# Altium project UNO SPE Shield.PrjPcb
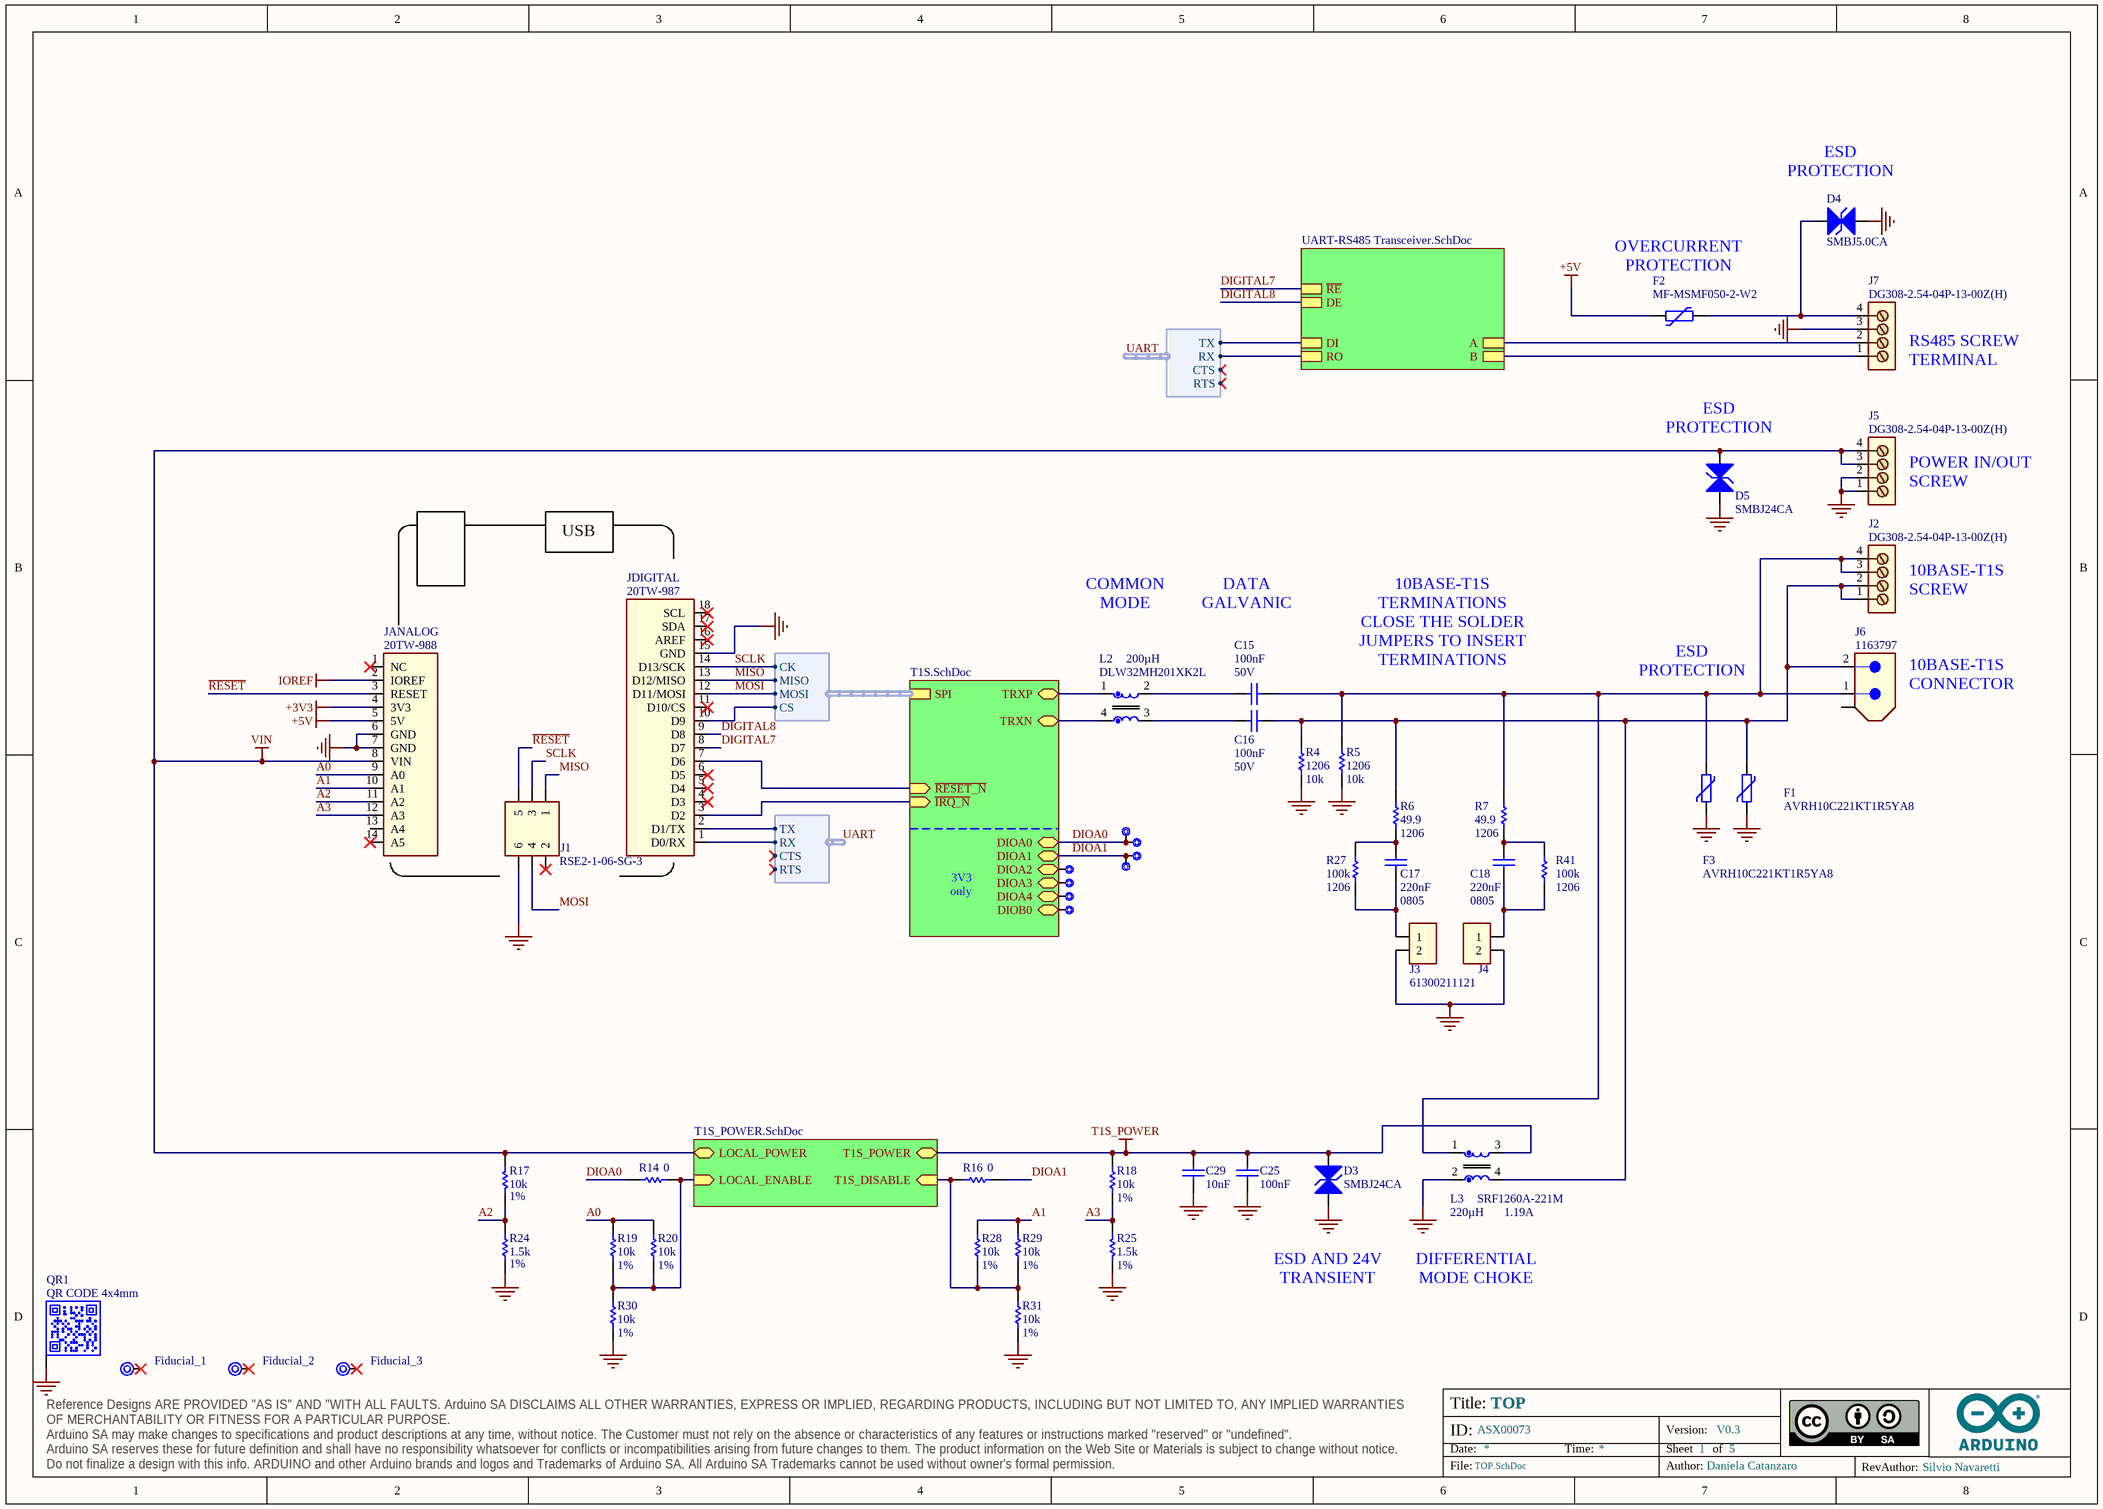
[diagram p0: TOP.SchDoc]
ASSEMBLY_BGA: _; ASSEMBLY_PRESSFIT: _; ASSEMBLY_SMD: X; ASSEMBLY_THT: X; BOARD_CODENAME: T2TOS; BOARD_INFO_AUTHOR: Daniela Catanzaro; BOARD_INFO_AUTHOR_REV: Silvio Navaretti; BOARD_INFO_Er: _; BOARD_INFO_FLEX: _; BOARD_INFO_FR4: X; BOARD_INFO_FR4_HTG: _; BOARD_INFO_IPC1: _; BOARD_INFO_IPC2: X; BOARD_INFO_IPC3: _; BOARD_INFO_IPC_NA: X; BOARD_INFO_NUMBER_OF_LAYERS: 4; BOARD_INFO_PCB_SIZE: 68.58x53.34mm; BOARD_INFO_POLYMIDE: _; BOARD_INFO_RIGID: X; BOARD_INFO_RIGID/FLEX: _; BOARD_INFO_TBD: _; BOARD_INFO_THICKNESS: 1.6mm; DRILLS_BLIND: _; DRILLS_BURIED: _; DRILLS_COPPER_FILLING: _; DRILLS_FULL: X; DRILLS_LASER: _; DRILLS_PRESSFIT: _; DRILLS_RESIN_FILLING: _; DRILLS_SLOT: _; DRILLS_SOLDER_FILLING: X; FINISH_ADJUSTMENTS: _; FINISH_EDGE_PLATING: _; FINISH_ENIG: _; FINISH_HAL: _; FINISH_HAL_LF: X; FINISH_NI/AU: _; FINISH_SILK_BOTTOM: X; FINISH_SILK_COLOR: WHITE; FINISH_SILK_TOP: X; FINISH_SN/PB: _; FINISH_SOLDERMASK_BOTTOM: X; FINISH_SOLDERMASK_COLOR: BLUE; FINISH_SOLDERMASK_PEELABLE_BOTTOM: _; FINISH_SOLDERMASK_PEELABLE_COLOR: _; FINISH_SOLDERMASK_PEELABLE_TOP: _; FINISH_SOLDERMASK_TOP: X; FINISH_TABS: _; FINISH_TBD: _; INSULATION_MIN_INNER: 0.127mm; INSULATION_MIN_OUTER: 0.127mm; PANEL_MILLING: X; PANEL_NOT_REQUESTED: _; PANEL_NUMBER_OF_FIGURES: 10; PANEL_PROVIDED: X; PANEL_REQUESTED: _; PANEL_SCORING: X; PANEL_SIZE: 284.7x157.16mm; PANEL_TABS: _; SKU: ASX00073; TRACK_MIN_WIDTH_INNER: 0.127mm; TRACK_MIN_WIDTH_OUTER: 0.127mm; Version: V0.3; VIA_1: _; VIA_1_HOLE_MM: _; VIA_1_PAD_MM: _; VIA_2: _; VIA_2_HOLE_MM: _; VIA_2_PAD_MM: _; VIA_3: _; VIA_3_HOLE_MM: _; VIA_3_PAD_MM: _; VIA_4: _; VIA_4_HOLE_MM: _; VIA_4_PAD_MM: _; VIA_5: _; VIA_5_HOLE_MM: _; VIA_5_PAD_MM: _; VIA_THROUGH: X; VIA_THROUGH_HOLE_MM: 0.3; VIA_THROUGH_PAD_MM: 0.6
5 sheets, 137 parts. Net scope: hierarchical (ports join the sheet entries above them; power ports are global).
Board files: PCB.PcbDoc, PANEL.PcbDoc
Sheets:
  TOP.SchDoc
    U_T1S = T1S.SchDoc
    U_T1S_POWER = T1S_POWER.SchDoc
      U_SWITCH = SWITCH.SchDoc
      U_SWITCH = SWITCH.SchDoc
    U_UART-RS485 Transceiver = UART-RS485 Transceiver.SchDoc

## Sheet TOP.SchDoc: TOP
size A3; DrawnBy: Silvio Navaretti; Engineer: Silvio Navaretti; DocumentNumber: AFX000070; SheetNumber: 1; SheetTotal: 5; RevAuthor: Silvio Navaretti

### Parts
C15  value 100nF  Voltage: 50V  [CAP-0805]  (hidden comment: 08055C104K4T2A)
C16  value 100nF  Voltage: 50V  [CAP-0805]  (hidden comment: 08055C104K4T2A)
C17  value 220nF  Case Code (Imperial): 0805  [CAP-0805]  (hidden comment: CL21B224KBFNNNF)
C18  value 220nF  Case Code (Imperial): 0805  [CAP-0805]  (hidden comment: CL21B224KBFNNNF)
C25  value 100nF  [CAP-0402]  (hidden comment: GRM155R61H104KE19D)
C29  value 10nF  [CAP-0402]  (hidden comment: C1005B103K500NT)
D3  SMBJ24CA  [SMB_NOPOLARITY]
D4  SMBJ5.0CA  [SMB_NOPOLARITY]
D5  SMBJ24CA  [SMB_NOPOLARITY]
DIO_B0  Test point 1.00mm  [TP-1.00MM]  (value not drawn)  (no BOM)
DIOA0  Test point 1.00mm  [TP-1.00MM]  (value not drawn)  (no BOM)
DIOA0_1  Test point 1.00mm  [TP-1.00MM]  (value not drawn)  (no BOM)
DIOA1  Test point 1.00mm  [TP-1.00MM]  (value not drawn)  (no BOM)
DIOA1_1  Test point 1.00mm  [TP-1.00MM]  (value not drawn)  (no BOM)
DIOA2  Test point 1.00mm  [TP-1.00MM]  (value not drawn)  (no BOM)
DIOA3  Test point 1.00mm  [TP-1.00MM]  (value not drawn)  (no BOM)
DIOA4  Test point 1.00mm  [TP-1.00MM]  (value not drawn)  (no BOM)
F1  AVRH10C221KT1R5YA8  [PASSIVE 0402]
F2  MF-MSMF050-2-W2  [1812]
F3  AVRH10C221KT1R5YA8  [PASSIVE 0402]
Fiducial_1  Fiducial mark 1mm with 2mm solder  [Fiducial mark 1mm with circle-Footprint-1]  (value not drawn)  (no BOM)
Fiducial_2  Fiducial mark 1mm with 2mm solder  [Fiducial mark 1mm with circle-Footprint-1]  (value not drawn)  (no BOM)
Fiducial_3  Fiducial mark 1mm with 2mm solder  [Fiducial mark 1mm with circle-Footprint-1]  (value not drawn)  (no BOM)
J1  RSE2-1-06-SG-3  [RSE2-1-06-SG-3]
J2  DG308-2.54-04P-13-00Z(H)  [DG308-2.54-04P]
J3  61300211121  [61300211121]
J4  61300211121  [61300211121]  (value not drawn)
J5  DG308-2.54-04P-13-00Z(H)  [DG308-2.54-04P]
J6  1163797  [1163797]
J7  DG308-2.54-04P-13-00Z(H)  [DG308-2.54-04P]
JANALOG  20TW-988  [20TW-988]
JDIGITAL  20TW-987  [20TW-987]
L2  DLW32MH201XK2L  Inductance: 200µH  [DLW32MH]
L3  SRF1260A-221M  Inductance: 220µH  IRMS: 1.19A  [SRF1260]
QR1  QR CODE 4x4mm  [QR CODE 4x4mm]  (no BOM)
R4  value 10k  Case Code (Imperial): 1206  [RES-1206]  (hidden comment: RC1206FR-0710KL)
R5  value 10k  Case Code (Imperial): 1206  [RES-1206]  (hidden comment: RC1206FR-0710KL)
R6  value 49.9  Case Code (Imperial): 1206  [RES-1206]  (hidden comment: RC1206FR-0749R9L)
R7  value 49.9  Case Code (Imperial): 1206  [RES-1206]  (hidden comment: RC1206FR-0749R9L)
R14  value 0  [RES-0603]  (hidden comment: CRCW06030000Z0EAC)
R16  value 0  [RES-0603]  (hidden comment: CRCW06030000Z0EAC)
R17  value 10k  Tolerance: 1%  [RES-0402]  (hidden comment: CRCW040210K0FKED)
R18  value 10k  Tolerance: 1%  [RES-0402]  (hidden comment: CRCW040210K0FKED)
R19  value 10k  Tolerance: 1%  [RES-0402]  (hidden comment: CRCW040210K0FKED)
R20  value 10k  Tolerance: 1%  [RES-0402]  (hidden comment: CRCW040210K0FKED)
R24  value 1.5k  Tolerance: 1%  [RES-0402]  (hidden comment: CRCW04021K50JNED)
R25  value 1.5k  Tolerance: 1%  [RES-0402]  (hidden comment: CRCW04021K50JNED)
R27  value 100k  Case Code (Imperial): 1206  [RES-1206]  (hidden comment: RV1206FR-07100KL)
R28  value 10k  Tolerance: 1%  [RES-0402]  (hidden comment: CRCW040210K0FKED)
R29  value 10k  Tolerance: 1%  [RES-0402]  (hidden comment: CRCW040210K0FKED)
R30  value 10k  Tolerance: 1%  [RES-0402]  (hidden comment: CRCW040210K0FKED)
R31  value 10k  Tolerance: 1%  [RES-0402]  (hidden comment: CRCW040210K0FKED)
R41  value 100k  Case Code (Imperial): 1206  [RES-1206]  (hidden comment: RV1206FR-07100KL)

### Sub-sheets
U_T1S = T1S.SchDoc: SPI (harness SPI), ~{RESET_N} (in), ~{IRQ_N} (in), DIOA0 (bidir), DIOA1 (bidir), DIOA2 (bidir), DIOA3 (bidir), DIOA4 (bidir), DIOB0 (bidir), TRXP (bidir), TRXN (bidir)
U_T1S_POWER = T1S_POWER.SchDoc: T1S_DISABLE (in), LOCAL_ENABLE (in), LOCAL_POWER (bidir), T1S_POWER (bidir)
U_UART-RS485 Transceiver = UART-RS485 Transceiver.SchDoc: B, A, ~{RE}, DE, DI, RO

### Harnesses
SPI: CS, CK, MISO, MOSI
UART: RX, TX, RTS, CTS

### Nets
+3V3: JANALOG.4(3V3)
+5V: F2.1 JANALOG.5(5V)
GND: C25.1 C29.1 D3.2(A2) D4.1(A1) D5.2(A2) F1.1 F3.1 J1.6 J3.2 J4.2 J5.1 J5.2 J7.3 JANALOG.6(GND) JANALOG.7(GND) JDIGITAL.15(GND) L3.2 QR1.PAD R4.2 R5.2 R24.1 R25.1 R30.1 R31.1
IOREF: JANALOG.2(IOREF)
T1S_POWER: C25.2 C29.2 D3.1(A1) L3.3 R18.2 ; sheet U_T1S_POWER/T1S_POWER
VIN: D5.1(A1) J5.3 J5.4 JANALOG.8(VIN) R17.2 ; sheet U_T1S_POWER/LOCAL_POWER
A0: JANALOG.9(A0) R19.2 R20.2  [project net A0_1]
A1: JANALOG.10(A1) R28.2 R29.2  [project net A1_1]
A2: JANALOG.11(A2) R17.1 R24.2  [project net A2_1]
A3: JANALOG.12(A3) R18.1 R25.2  [project net A3_1]
DIGITAL7: JDIGITAL.8(D7) ; sheet U_UART-RS485 Transceiver/~{RE}
DIGITAL8: JDIGITAL.9(D8) ; sheet U_UART-RS485 Transceiver/DE
DIOA0: DIOA0.X DIOA0_1.X R14.1 ; sheet U_T1S/DIOA0
DIOA1: DIOA1.X DIOA1_1.X R16.2 ; sheet U_T1S/DIOA1
MISO: J1.1 JDIGITAL.13(D12/MISO) ; sheet U_T1S/SPI.MISO
MOSI: J1.4 JDIGITAL.12(D11/MOSI) ; sheet U_T1S/SPI.MOSI
~{RESET}: J1.5 JANALOG.3(RESET)  [project net ~{RESET}_1]
SCLK: J1.3 JDIGITAL.14(D13/SCK) ; sheet U_T1S/SPI.CK
UART.RX: JDIGITAL.1(D0/RX) ; sheet U_UART-RS485 Transceiver/RO, harness UART.RX
UART.TX: JDIGITAL.2(D1/TX) ; sheet U_UART-RS485 Transceiver/DI, harness UART.TX
NetC15_1: C15.1 L2.2
NetC15_2: C15.2 F3.2 J2.3 J2.4 J6.1 L3.1 R5.1 R7.1
NetC16_1: C16.1 L2.3
NetC16_2: C16.2 F1.2 J2.1 J2.2 J6.2 L3.4 R4.1 R6.1
NetC17_1: C17.1 R6.2 R27.1
NetC17_2: C17.2 J3.1 R27.2
NetC18_1: C18.1 R7.2 R41.1
NetC18_2: C18.2 J4.1 R41.2
NetD4_2: D4.2(A2) F2.2 J7.4
NetDIO_B0_X: DIO_B0.X ; sheet U_T1S/DIOB0
NetDIOA2_X: DIOA2.X ; sheet U_T1S/DIOA2
NetDIOA3_X: DIOA3.X ; sheet U_T1S/DIOA3
NetDIOA4_X: DIOA4.X ; sheet U_T1S/DIOA4
NetJ7_1: J7.1 ; sheet U_UART-RS485 Transceiver/B
NetJ7_2: J7.2 ; sheet U_UART-RS485 Transceiver/A
NetJDIGITAL_3: JDIGITAL.3(D2) ; sheet U_T1S/~{IRQ_N}
NetJDIGITAL_7: JDIGITAL.7(D6) ; sheet U_T1S/~{RESET_N}
NetJDIGITAL_10: JDIGITAL.10(D9) ; sheet U_T1S/SPI.CS
NetL2_1: L2.1 ; sheet U_T1S/TRXP
NetL2_4: L2.4 ; sheet U_T1S/TRXN
NetQ1_1: R16.1 R28.1 R29.1 R31.2 ; sheet U_T1S_POWER/T1S_DISABLE
NetR14_2: R14.2 R19.1 R20.1 R30.2 ; sheet U_T1S_POWER/LOCAL_ENABLE

Not connected (* = marked no-connect by the designer): Fiducial_1 1*; Fiducial_2 1*; Fiducial_3 1*; J1 2*; J6 SHIELD; JANALOG 1(NC)* 13(A4) 14(A5)*; JDIGITAL 4(D3)* 5(D4)* 6(D5)* 11(D10/CS)* 16(AREF)* 17(SDA)* 18(SCL)*

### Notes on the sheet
- (near D4) ESD PROTECTION
- (near F2) OVERCURRENT PROTECTION
- (near J7) RS485 SCREW TERMINAL
- (near D5) ESD PROTECTION
- (near J5) POWER IN/OUT SCREW TERMINAL
- USB
- COMMON MODE
  CHOKE
- DATA GALVANIC ISOLATION
- (near J2) 10BASE-T1S SCREW TERMINAL
- 10BASE-T1S TERMINATIONS CLOSE THE SOLDER JUMPERS TO INSERT TERMINATIONS
- ESD PROTECTION
- 10BASE-T1S CONNECTOR
- 3V3
  only
- ESD AND 24V TRANSIENT PROTECTION
- DIFFERENTIAL MODE CHOKE

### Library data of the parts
C15 C16 = C0148-A.1: CAP CHIP 0805 100nF 10% 50V X7R; Manufacturer: KYOCERA AVX; Code Arduino: C0148
C17 C18 = C0048-A.5: CAP CHIP 0805 220nF 10% 50V X5R; Manufacturer: Samsung Electro-Mechanics; Code Arduino: C0048
C25 = C0015-A.14: CAP CHIP 0402 100nF 10% 50V X5R; Manufacturer: Murata; Code Arduino: A5141
C29 = C0009-A.15: CAP CHIP 0402 10nF 10% 50V X7R; Manufacturer: Hottech; Code Arduino: 0165
D3 D5 = D0070-A.2: TVS BIDIRECTIONAL SMD Vr 24V, Vbr min 26.7V, 600W, SMB; Manufacturer: Littlefuse; Code Arduino: D0070; V(BR) Typ (V): 26.7
D4 = D0077-A.1: TVS BIDIRECTIONAL SMD Vr 5V, Vbr min 6.4V, 600W, SMB; Manufacturer: Littelfuse; Code Arduino: D0077
DIO_B0 DIOA0 DIOA0_1 DIOA1 DIOA1_1 DIOA2-DIOA4 = UT0013-A.6: Manufacturer: This is not a component
F1 F3 = P0023-1: VARISTOR 0402, VDC 70V, 1.5pF; Manufacturer: TDK; Code Arduino: P0023
F2 = P0002-A.7: PTC RESET FUSE 15V 500MA 1812 LOGO OO ARDUINO; Manufacturer: Bourns; Approvals: UL,CSA,TUV; Time to Trip: 0.15s; Max Current Rating: 100A; Trip Current: 1A; Resistance: 150mR; Code Arduino: 3335; Power Dissipation: 800mW
Fiducial_1-Fiducial_3 = UT0024-A.6
J1 = J0481-A.2: CONN header 2.54mm, 2x3 positions, female heigth 8.5mm male heigth 11.4mm; Manufacturer: Adam Tech; Code Arduino: J0481
J2 J5 J7 = J0438-A.5: CONN SCREW TERMINAL 4 POS pitch 2.54mm height 8.6mm BLACK; Manufacturer: Degson; Code Arduino: J0438
J3 J4 = J0182-A.4: CONN HEADER MALE VERT 2POS 2.54MM; Manufacturer: Wurth Electronics; Code Arduino: 2273
J6 = J0425-A.5: CONN 10BASE-T1S, CatB, Single Pair Ethernet; Manufacturer: Phoenix; Code Arduino: J0425
JANALOG = J0407-A.8: JANALOG UNO SHIELDS header 2.54mm with 8+6 pins, custom 5.08mm pitch between them, custom silkscreen print on side, custom 14.95mm pins length; Manufacturer: 4UCONN; Code Arduino: 3711
JDIGITAL = J0408-A.7: JDIGITAL UNO SHIELDS header 2.54mm with 8+10 pins, custom 4.06mm pitch between them, custom silkscreen print on side, custom 14.95mm pins length; Manufacturer: 4UCONN; Code Arduino: 3712
L2 = I0108-A.2: CHOKE SMD 200uH at 0.1MHz, 70mA DC 4R 3.2x2.2x2.5mm; Manufacturer: Murata; Code Arduino: I0108
L3 = I0110-A.2: COUPLED INDUCTORS SMD Parallel 220uH, IRMS 1.19A, ISAT 1.51A, DCR 1R41 12.5x12.5x6mm; Manufacturer: Bourns; DCR max: 1.41; Code Arduino: I0110; Tolerance: 20%
QR1 = QR-0001-A.3: QR CODE 4x4mm on layer 34 (This is not a component); Code Arduino: QRCODE_4x4mm
R4 R5 = R0298-A.1: RES CHIP 1206 10k 1% 1/4W; Manufacturer: YAGEO; Code Arduino: R0298; Power: 250mW; Temperature coefficient: 100ppm
R6 R7 = R0301-A.1: RES CHIP 1206 49R9 1% 1/4W; Manufacturer: YAGEO; Power: 250mW; Temperature coefficient: 100ppm; Code Arduino: R0301
R14 R16 = R0096-A.22: RES CHIP 0603 0R 1/10W; Manufacturer: Vishay; Power: 100mW; Code Arduino: 0233; Tolerance: 0%; Temperature coefficient: 0ppm
R17-R20 R28-R31 = R0003-A.24: RES CHIP 0402 10k 1% 1/16W; Manufacturer: Vishay; Code Arduino: 0136; Power: 62.5mW; Temperature coefficient: 100ppm
R24 R25 = R0224-A.11: RES CHIP 0402 1k5 1% 1/16W; Manufacturer: Vishay; Power: 62.5mW; Code Arduino: R0224; Temperature coefficient: 200ppm
R27 R41 = R0349-A.1: RES CHIP 1206 100k 1% 1/4W; Manufacturer: YAGEO; Power: 250mW; Temperature coefficient: 200ppm; Code Arduino: R0349

## Sheet T1S.SchDoc: T1S
size A4; DrawnBy: Silvio Navaretti; Engineer: Silvio Navaretti; DocumentNumber: AFX000070; SheetNumber: 2; SheetTotal: 5; RevAuthor: Silvio Navaretti
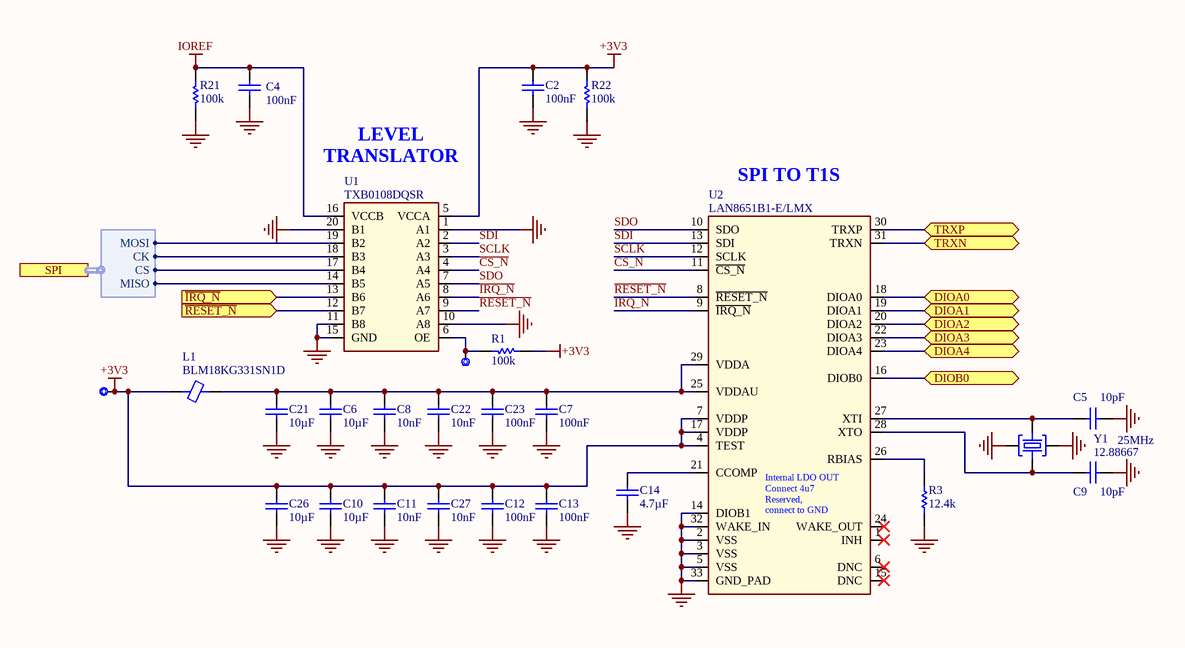
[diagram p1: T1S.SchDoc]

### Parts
C2  value 100nF  [CAP-0402]  (hidden comment: GRM155R61H104KE19D)
C4  value 100nF  [CAP-0402]  (hidden comment: GRM155R61H104KE19D)
C5  value 10pF  [CAP-0402]  (hidden comment: C0402H100J5GACTU)
C6  value 10µF  [CAP-0402]  (hidden comment: GRM155R60J106ME05D)
C7  value 100nF  [CAP-0402]  (hidden comment: GRM155R61H104KE19D)
C8  value 10nF  [CAP-0402]  (hidden comment: C1005B103K500NT)
C9  value 10pF  [CAP-0402]  (hidden comment: C0402H100J5GACTU)
C10  value 10µF  [CAP-0402]  (hidden comment: GRM155R60J106ME05D)
C11  value 10nF  [CAP-0402]  (hidden comment: C1005B103K500NT)
C12  value 100nF  [CAP-0402]  (hidden comment: GRM155R61H104KE19D)
C13  value 100nF  [CAP-0402]  (hidden comment: GRM155R61H104KE19D)
C14  value 4.7µF  [CAP-0603]  (hidden comment: GRM188R61C475KAAJD)
C21  value 10µF  [CAP-0402]  (hidden comment: GRM155R60J106ME05D)
C22  value 10nF  [CAP-0402]  (hidden comment: C1005B103K500NT)
C23  value 100nF  [CAP-0402]  (hidden comment: GRM155R61H104KE19D)
C26  value 10µF  [CAP-0402]  (hidden comment: GRM155R60J106ME05D)
C27  value 10nF  [CAP-0402]  (hidden comment: C1005B103K500NT)
L1  BLM18KG331SN1D  [L-0603]
R1  value 100k  [RES-0402]  (hidden comment: CRCW0402100KFKEDC)
R3  value 12.4k  [RES-0402]  (hidden comment: CRCW040212K4FKED)
R21  value 100k  [RES-0402]  (hidden comment: CRCW0402100KFKEDC)
R22  value 100k  [RES-0402]  (hidden comment: CRCW0402100KFKEDC)
T1S_POWER  Test point 1.00mm  [TP-1.00MM]  (value not drawn)  (no BOM)
TRANSLATOR_OE  Test point 1.00mm  [TP-1.00MM]  (value not drawn)  (no BOM)
U1  TXB0108DQSR  [FP-DQS0020A-MFG]
U2  LAN8651B1-E/LMX  [PQFN50P500X500X100_HS-33N]
Y1  12.88667  Frequency: 25MHz  [CRYSTAL3.2X2.5]

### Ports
DIOA0 (bidir), DIOA1 (bidir), DIOA2 (bidir), DIOA3 (bidir), DIOA4 (bidir), DIOB0 (bidir), SPI (harness SPI), TRXN (bidir), TRXP (bidir), ~{IRQ_N} (in), ~{RESET_N} (in)

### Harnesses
SPI: CS, CK, MISO, MOSI

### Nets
+3V3: C2.2 C10.2 C11.2 C12.2 C13.2 C26.2 C27.2 L1.1 R1.1 R22.1 T1S_POWER.X U1.5(VCCA) U2.4(TEST) U2.7(VDDP) U2.17(VDDP)
GND: C2.1 C4.1 C5.1 C6.1 C7.1 C8.1 C9.1 C10.1 C11.1 C12.1 C13.1 C14.1 C21.1 C22.1 C23.1 C26.1 C27.1 R3.2 R21.2 R22.2 U1.1(A1) U1.10(A8) U1.11(B8) U1.15(GND) U1.20(B1) U2.2(VSS) U2.3(VSS) U2.5(VSS) U2.14(DIOB1) U2.32(WAKE_IN) U2.33(GND_PAD) Y1.2 Y1.4
IOREF: C4.2 R21.1 U1.16(VCCB)
~{CS_N}: U1.4(A4) U2.11(~{CS_N})  [project net ~{CS_N}_2]
DIOA0: U2.18(DIOA0) ; port DIOA0
DIOA1: U2.19(DIOA1) ; port DIOA1
~{IRQ_N}: U1.8(A6) U2.9(~{IRQ_N})  [project net ~{IRQ_N}_2]
MISO: U1.14(B5) ; port SPI.MISO
MOSI: U1.19(B2) ; port SPI.MOSI
~{RESET_N}: U1.9(A7) U2.8(~{RESET_N})  [project net ~{RESET_N}_2]
SCLK: U1.18(B3) ; port SPI.CK
SCLK: U1.3(A3) U2.12(SCLK)  [project net SCLK_2]  [a separate net that carries the same name]
SDI: U1.2(A2) U2.13(SDI)  [project net SDI_2]
SDO: U1.7(A5) U2.10(SDO)  [project net SDO_2]
NetC5_2: C5.2 U2.27(XTI) Y1.3
NetC6_2: C6.2 C7.2 C8.2 C21.2 C22.2 C23.2 L1.2 U2.25(VDDAU) U2.29(VDDA)
NetC9_2: C9.2 U2.28(XTO) Y1.1
NetC14_2: C14.2 U2.21(CCOMP)
NetDIO_B0_X: U2.16(DIOB0) ; port DIOB0
NetDIOA2_X: U2.20(DIOA2) ; port DIOA2
NetDIOA3_X: U2.22(DIOA3) ; port DIOA3
NetDIOA4_X: U2.23(DIOA4) ; port DIOA4
NetJDIGITAL_3: U1.13(B6) ; port ~{IRQ_N}
NetJDIGITAL_7: U1.12(B7) ; port ~{RESET_N}
NetJDIGITAL_10: U1.17(B4) ; port SPI.CS
NetL2_1: U2.30(TRXP) ; port TRXP
NetL2_4: U2.31(TRXN) ; port TRXN
NetR1_2: R1.2 TRANSLATOR_OE.X U1.6(OE)
NetR3_1: R3.1 U2.26(RBIAS)

Not connected (* = marked no-connect by the designer): U2 1(INH)* 6(DNC)* 15(DNC)* 24(WAKE_OUT)*

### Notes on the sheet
- LEVEL TRANSLATOR
- (near U2) SPI TO T1S

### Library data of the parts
C2 C4 C7 C12 C13 C23 = C0015-A.14: as C25 on sheet TOP
C5 C9 = C0006-A.14: CAP CHIP 0402 10pF 5% 50V C0G; Manufacturer: KEMET; Code Arduino: 3382
C6 C10 C21 C26 = C0091-A.13: CAP CHIP 0402 10uF 20% X5R 6.3V; Manufacturer: Murata; Code Arduino: C0091
C8 C11 C22 C27 = C0009-A.15: as C29 on sheet TOP
C14 = C0054-A.16: CAP CHIP 0603 4.7uF 10% 16V X5R; Manufacturer: Murata; Code Arduino: A5072
L1 = I0002-A.7: FERRITE SMD 0603 330 OHM 1LN; Manufacturer: Murata; Max DC Current: 1.7A; DC Resistance (DCR): 80mR; Tolerance: 25%; Code Arduino: A5059; Test Frequency: 100MHz
R1 R21 R22 = R0001-A.24: RES CHIP 0402 100k 1% 1/16W; Manufacturer: Vishay; Code Arduino: 0134; Power: 62.5mW; Temperature coefficient: 100ppm
R3 = R0027-A.24: RES CHIP 0402 12k4 1% 1/16W; Manufacturer: Vishay; Power: 62.5mW; Temperature coefficient: 100ppm; Code Arduino: 2297
T1S_POWER TRANSLATOR_OE = UT0013-A.6: Manufacturer: This is not a component
U1 = U0276-A.5: IC TRANSLATOR LEVEL SHIFTER BIDIR 8BIT 20SON; Manufacturer: Texas Instruments; Code Arduino: U0276
U2 = U0362-A.7: IC 10BASE T1S MAC PHY Ethernet 10Mb Controller, SPI, internal LDO, VQFN 5x5mm; Manufacturer: Microchip; Code Arduino: U0362
Y1 = X0027-A.4: CRYSTAL 25MHz, frequency tolerance +-30ppm, temperature tolerance +-50ppm, load capacitance 12pF, aging +-2ppm 3.2x2.5mm; Manufacturer: GEYER; Code Arduino: 0846

## Sheet T1S_POWER.SchDoc: POWER SWITCHES
size A4; DrawnBy: Silvio Navaretti; Engineer: Silvio Navaretti; DocumentNumber: AFX000070; SheetNumber: 3; SheetTotal: 5; RevAuthor: Silvio Navaretti
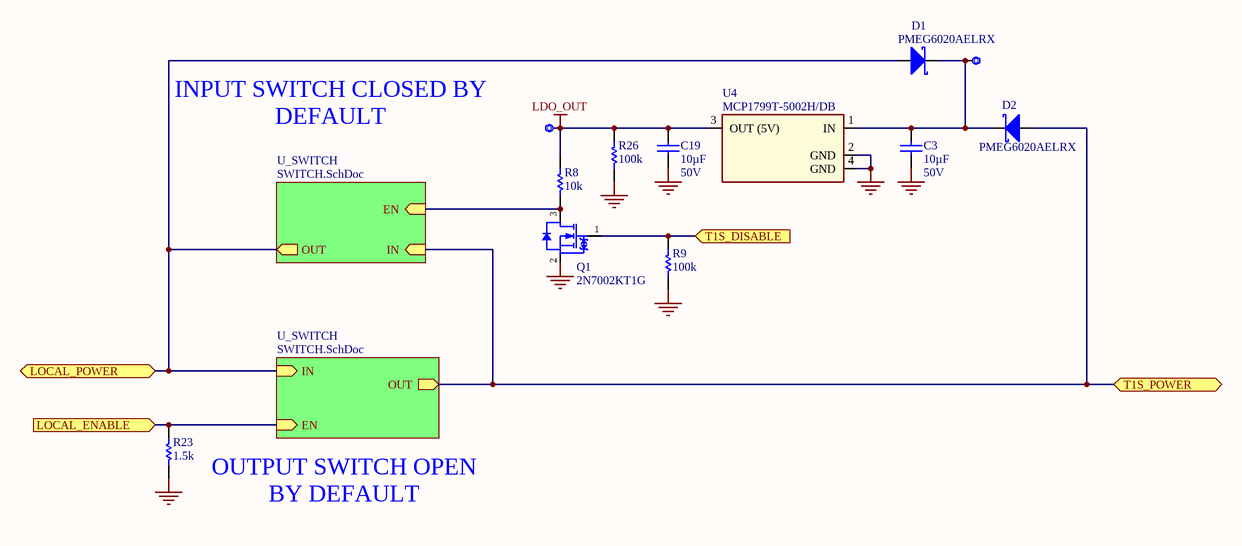
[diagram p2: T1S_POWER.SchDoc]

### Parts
C3  value 10µF  Voltage: 50V  [CAP-0805]  (hidden comment: GRM21BR61H106ME43L)
C19  value 10µF  Voltage: 50V  [CAP-0805]  (hidden comment: GRM21BR61H106ME43L)
D1  PMEG6020AELRX  [SOD123-1]
D2  PMEG6020AELRX  [SOD123-1]
LDO_OUT  Test point 1.00mm  [TP-1.00MM]  (value not drawn)  (no BOM)
POWER_OR  Test point 1.00mm  [TP-1.00MM]  (value not drawn)  (no BOM)
Q1  2N7002KT1G  [SOT23]
R8  value 10k  [RES-0402]  (hidden comment: CRCW040210K0FKED)
R9  value 100k  [RES-0402]  (hidden comment: CRCW0402100KFKEDC)
R23  value 1.5k  [RES-0402]  (hidden comment: CRCW04021K50JNED)
R26  value 100k  [RES-0402]  (hidden comment: CRCW0402100KFKEDC)
U4  MCP1799T-5002H/DB  [SOT223-3]

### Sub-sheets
U_SWITCH = SWITCH.SchDoc: OUT (out), EN (in), IN (in)
U_SWITCH = SWITCH.SchDoc: OUT (out), EN (in), IN (in)

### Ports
LOCAL_ENABLE (in), LOCAL_POWER (bidir), T1S_DISABLE (in), T1S_POWER (bidir)

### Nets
GND: C3.2 C19.2 Q1.2(S) R9.2 R23.2 R26.2 U4.2(GND) U4.4(GND)
LDO_OUT: C19.1 LDO_OUT.X R8.1 R26.1 U4.3(OUT_(5V))
T1S_POWER: D2.A ; port T1S_POWER, sheet U_SWITCH/OUT, sheet U_SWITCH/IN
VIN: D1.A ; port LOCAL_POWER, sheet U_SWITCH/IN, sheet U_SWITCH/OUT
NetC3_1: C3.1 D1.C D2.C POWER_OR.X U4.1(IN)
NetQ1_1: Q1.1(G) R9.1 ; port T1S_DISABLE
NetQ1_3: Q1.3(D) R8.2 ; sheet U_SWITCH/EN
NetR14_2: R23.1 ; port LOCAL_ENABLE, sheet U_SWITCH/EN

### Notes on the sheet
- INPUT SWITCH CLOSED BY DEFAULT
- (near R23) OUTPUT SWITCH OPEN BY DEFAULT

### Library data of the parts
C3 C19 = C0158-A.3: CAP CHIP 0805 10uF 20% 50V X5R; Manufacturer: Murata Electronics; Code Arduino: C0158
D1 D2 = D0026-A.6: DIODE SCHOTTKY SMD 2A 60V SOD123FL; Manufacturer: Nexperia; Manucturer Part Number 2: SS26L; Code Arduino: 2208; Manucturer 2: Hottech; Forward Voltage: 0.6V
LDO_OUT POWER_OR = UT0013-A.6: Manufacturer: This is not a component
Q1 = T0004-A.10: MOSFET N-CH 60V 300mA ESD prot. SOT23; Manufacturer: On Semiconductor; Device Type: Mosfet N-CH SMD; Code Arduino: A5393
R8 = R0003-A.24: as R17 on sheet TOP
R9 R26 = R0001-A.24: as R1 on sheet T1S
R23 = R0224-A.11: RES CHIP 0402 1k5 1% 1/16W; Manufacturer: Vishay; Code Arduino: R0224; Power: 62.5mW; Temperature coefficient: 200ppm
U4 = U0411-A.1: IC LINEAR REGULATOR Vout 5V fixed Vin max 45V Iout max 80mA SOT223-3; Manufacturer: Microchip; Code Arduino: U0411

## Sheet SWITCH.SchDoc: SWITCH
size A4; DrawnBy: Silvio Navaretti; Engineer: Silvio Navaretti; DocumentNumber: AFX000070; SheetNumber: 4; SheetTotal: 5; RevAuthor: Silvio Navaretti
Used 2 times, as channels U_T1S_POWER/U_SWITCH, U_T1S_POWER/U_SWITCH. Parts and nets are listed once, with the designators drawn on the sheet.
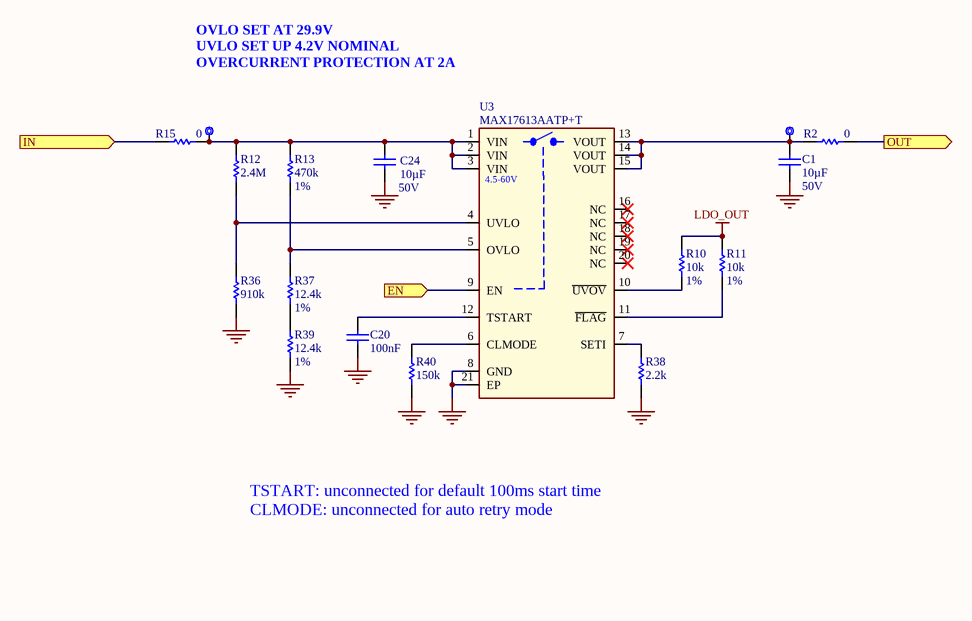
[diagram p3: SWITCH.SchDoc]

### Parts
C1  value 10µF  Voltage: 50V  [CAP-0805]  (hidden comment: GRM21BR61H106ME43L)
C20  value 100nF  [CAP-0402]  (hidden comment: GRM155R61H104KE19D)
C24  value 10µF  Voltage: 50V  [CAP-0805]  (hidden comment: GRM21BR61H106ME43L)
IN  Test point 1.00mm  [TP-1.00MM]  (value not drawn)  (no BOM)
OUT  Test point 1.00mm  [TP-1.00MM]  (value not drawn)  (no BOM)
R2  value 0  [RES-0603]  (hidden comment: CRCW06030000Z0EAC)
R10  value 10k  Tolerance: 1%  [RES-0402]  (hidden comment: CRCW040210K0FKED)
R11  value 10k  Tolerance: 1%  [RES-0402]  (hidden comment: CRCW040210K0FKED)
R12  value 2.4M  [RES-0402]  (hidden comment: RC0402FR-072M4L)
R13  value 470k  Tolerance: 1%  [RES-0603]  (hidden comment: RC0603FR-07470KL)
R15  value 0  [RES-0603]  (hidden comment: CRCW06030000Z0EAC)
R36  value 910k  [RES-0402]  (hidden comment: CRCW0402910KFKED)
R37  value 12.4k  Tolerance: 1%  [RES-0402]  (hidden comment: CRCW040212K4FKED)
R38  value 2.2k  [RES-0603]  (hidden comment: CRCW06032K20FKEAC)
R39  value 12.4k  Tolerance: 1%  [RES-0402]  (hidden comment: CRCW040212K4FKED)
R40  value 150k  [RES-0402]  (hidden comment: RC0402JR-10150KL)
U3  MAX17613AATP+T  [QFN50P400X400X80_HS-21N]

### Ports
EN (in), IN (in), OUT (out)

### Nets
GND: C1.2 C20.1 C24.2 R36.1 R38.1 R39.1 R40.1 U3.8(GND) U3.21(EP)
LDO_OUT: R10.2 R11.2
EN: U3.9(EN) ; port EN
IN: R15.2 ; port IN
OUT: R2.1 ; port OUT
NetC1_1: C1.1 OUT.X R2.2 U3.13(VOUT) U3.14(VOUT) U3.15(VOUT)
NetC20_2: C20.2 U3.12(TSTART)
NetC24_1: C24.1 IN.X R12.2 R13.2 R15.1 U3.1(VIN) U3.2(VIN) U3.3(VIN)
NetR10_1: R10.1 U3.10(~{UVOV})
NetR11_1: R11.1 U3.11(~{FLAG})
NetR12_1: R12.1 R36.2 U3.4(UVLO)
NetR13_1: R13.1 R37.2 U3.5(OVLO)
NetR37_1: R37.1 R39.2
NetR38_2: R38.2 U3.7(SETI)
NetR40_2: R40.2 U3.6(CLMODE)

Not connected (* = marked no-connect by the designer): U3 16(NC)* 17(NC)* 18(NC)* 19(NC)* 20(NC)*

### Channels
U_T1S_POWER/U_SWITCH: designators end in _2; ports EN=NetR14_2 IN=VIN OUT=T1S_POWER
U_T1S_POWER/U_SWITCH: designators end in _1; ports EN=NetQ1_3 IN=T1S_POWER OUT=VIN

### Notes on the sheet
- OVLO SET AT 29.9V
  UVLO SET UP 4.2V NOMINAL
  OVERCURRENT PROTECTION AT 2A
- TSTART: unconnected for default 100ms start time
  CLMODE: unconnected for auto retry mode

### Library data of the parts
C1 C24 = C0158-A.3: as C3 on sheet T1S_POWER
C20 = C0015-A.14: as C25 on sheet TOP
IN OUT = UT0013-A.6: Manufacturer: This is not a component
R2 R15 = R0096-A.22: RES CHIP 0603 0R 1/10W; Manufacturer: Vishay; Code Arduino: 0233; Power: 100mW; Tolerance: 0%; Temperature coefficient: 0ppm
R10 R11 = R0003-A.24: as R17 on sheet TOP
R12 = R0347-A.1: RES CHIP 0402 2.4M 1% 1/16W; Manufacturer: YAGEO; Temperature coefficient: 100ppm; Code Arduino: R0347; Power: 62.5mW
R13 = R0102-A.10: RES CHIP 0603 470k 1% 1/10W; Manufacturer: Yageo; Power: 100mW; Code Arduino: R0102; Temperature coefficient: 100ppm
R36 = R0041-A.24: RES CHIP 0402 910k 1% 1/16W; Manufacturer: Vishay; Temperature coefficient: 100ppm; Code Arduino: A5092; Power: 62.5mW
R37 R39 = R0027-A.24: RES CHIP 0402 12k4 1% 1/16W; Manufacturer: Vishay; Code Arduino: 2297; Power: 62.5mW; Temperature coefficient: 100ppm
R38 = R0113-A.22: RES CHIP 0603 2k2 1% 1/10W; Manufacturer: Vishay; Power: 100mW; Code Arduino: 0587; Temperature coefficient: 100ppm
R40 = R0335-A.1: RES CHIP 0402 150k 5% 1/16W; Manufacturer: YAGEO; Power: 62.5mW; Code Arduino: R0335; Temperature coefficient: 100ppm
U3 = U0397-A.7: IC Power switch high side, 4.5V to 60V, 3A current limiter, reverse current blocking, short circuit and over current protection, UVLO/OVLO, TQFN-EP 4x4mm; Manufacturer: Analog Devices; Code Arduino: U0397

## Sheet UART-RS485 Transceiver.SchDoc: UART-RS485 Transceiver
size A4; SheetNumber: 5; SheetTotal: 5
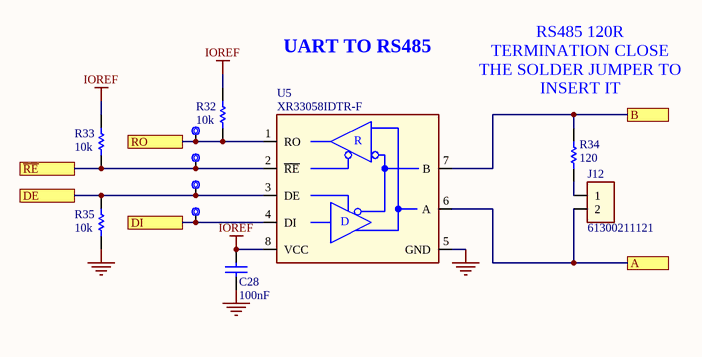
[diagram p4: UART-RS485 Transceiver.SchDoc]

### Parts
C28  value 100nF  [CAP-0402]  (hidden comment: GRM155R61H104KE19D)
DE  Test point 1.00mm  [TP-1.00MM]  (value not drawn)  (no BOM)
DI  Test point 1.00mm  [TP-1.00MM]  (value not drawn)  (no BOM)
J12  61300211121  [61300211121]
R32  value 10k  [RES-0402]  (hidden comment: CRCW040210K0FKED)
R33  value 10k  [RES-0402]  (hidden comment: CRCW040210K0FKED)
R34  value 120  [RES-0805]  (hidden comment: RMCF0805FT120R)
R35  value 10k  [RES-0402]  (hidden comment: CRCW040210K0FKED)
R\E\  Test point 1.00mm  [TP-1.00MM]  (value not drawn)  (no BOM)
RO  Test point 1.00mm  [TP-1.00MM]  (value not drawn)  (no BOM)
U5  XR33058IDTR-F  [SOIC8]

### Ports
A, B, DE, DI, RO, ~{RE}

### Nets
GND: C28.1 R35.1 U5.5(GND)
IOREF: C28.2 R32.2 R33.2 U5.8(VCC)
DIGITAL7: R33.1 R\E\.X U5.2(~{RE}) ; port ~{RE}
DIGITAL8: DE.X R35.2 U5.3(DE) ; port DE
UART.RX: R32.1 RO.X U5.1(RO) ; port RO
UART.TX: DI.X U5.4(DI) ; port DI
NetJ7_1: R34.2 U5.7(B) ; port B
NetJ7_2: J12.2 U5.6(A) ; port A
NetJ12_1: J12.1 R34.1

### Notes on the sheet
- UART TO RS485
- RS485 120R TERMINATION CLOSE THE SOLDER JUMPER TO INSERT IT

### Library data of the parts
C28 = C0015-A.14: as C25 on sheet TOP
DE DI R\E\ RO = UT0013-A.6: Manufacturer: This is not a component
J12 = J0182-A.4: as J3 on sheet TOP
R32 R33 R35 = R0003-A.24: RES CHIP 0402 10k 1% 1/16W; Manufacturer: Vishay; Power: 62.5mW; Code Arduino: 0136; Temperature coefficient: 100ppm
R34 = R0196-A.14: RES CHIP 0805 120R 1% 1/8W; Manufacturer: Stackpole Electronics; Code Arduino: R0196; Temperature coefficient: 100ppm; Power: 125mW
U5 = U0317-A.2: IC RS485/RS422 HALF DUPLEX 20Mbps, 80 nodes, failsafe +-60V, hot swap, ESD 15kV, -40 to 85 °C, PDSO8; Manufacturer: MaxLinear; Code Arduino: U0317

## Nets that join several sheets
+3V3: TOP (JANALOG.4), T1S (15 pins)
GND: TOP (24 pins), T1S (33 pins), T1S_POWER (8 pins), U_T1S_POWER/U_SWITCH (9 pins), U_T1S_POWER/U_SWITCH (9 pins), UART-RS485 Transceiver (C28.1 R35.1 U5.5)
IOREF: TOP (JANALOG.2), T1S (C4.2 R21.1 U1.16), UART-RS485 Transceiver (C28.2 R32.2 R33.2 U5.8)
LDO_OUT: T1S_POWER (5 pins), U_T1S_POWER/U_SWITCH (R10_2.2 R11_2.2), U_T1S_POWER/U_SWITCH (R10_1.2 R11_1.2)
T1S_POWER: TOP (5 pins), T1S_POWER (D2.A), U_T1S_POWER/U_SWITCH (R2_2.1), U_T1S_POWER/U_SWITCH (R15_1.2)
VIN: TOP (5 pins), T1S_POWER (D1.A), U_T1S_POWER/U_SWITCH (R15_2.2), U_T1S_POWER/U_SWITCH (R2_1.1)
DIGITAL7: TOP (JDIGITAL.8), UART-RS485 Transceiver (R33.1 R\E\.X U5.2)
DIGITAL8: TOP (JDIGITAL.9), UART-RS485 Transceiver (DE.X R35.2 U5.3)
DIOA0: TOP (DIOA0.X DIOA0_1.X R14.1), T1S (U2.18)
DIOA1: TOP (DIOA1.X DIOA1_1.X R16.2), T1S (U2.19)
MISO: TOP (J1.1 JDIGITAL.13), T1S (U1.14)
MOSI: TOP (J1.4 JDIGITAL.12), T1S (U1.19)
NetDIO_B0_X: TOP (DIO_B0.X), T1S (U2.16)
NetDIOA2_X: TOP (DIOA2.X), T1S (U2.20)
NetDIOA3_X: TOP (DIOA3.X), T1S (U2.22)
NetDIOA4_X: TOP (DIOA4.X), T1S (U2.23)
NetJ7_1: TOP (J7.1), UART-RS485 Transceiver (R34.2 U5.7)
NetJ7_2: TOP (J7.2), UART-RS485 Transceiver (J12.2 U5.6)
NetJDIGITAL_3: TOP (JDIGITAL.3), T1S (U1.13)
NetJDIGITAL_7: TOP (JDIGITAL.7), T1S (U1.12)
NetJDIGITAL_10: TOP (JDIGITAL.10), T1S (U1.17)
NetL2_1: TOP (L2.1), T1S (U2.30)
NetL2_4: TOP (L2.4), T1S (U2.31)
NetQ1_1: TOP (R16.1 R28.1 R29.1 R31.2), T1S_POWER (Q1.1 R9.1)
NetQ1_3: T1S_POWER (Q1.3 R8.2), U_T1S_POWER/U_SWITCH (U3_1.9)
NetR14_2: TOP (R14.2 R19.1 R20.1 R30.2), T1S_POWER (R23.1), U_T1S_POWER/U_SWITCH (U3_2.9)
SCLK: TOP (J1.3 JDIGITAL.14), T1S (U1.18)
UART.RX: TOP (JDIGITAL.1), UART-RS485 Transceiver (R32.1 RO.X U5.1)
UART.TX: TOP (JDIGITAL.2), UART-RS485 Transceiver (DI.X U5.4)

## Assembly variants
ASX00073: not fitted C20_1 C20_2 R19 R20 R28 R29 R30 R31 R40_1 R40_2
